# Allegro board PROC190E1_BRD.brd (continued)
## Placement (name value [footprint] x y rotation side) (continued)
R303  1.3K_1%  [RES0402_0-5]  21.9 58.09 180 top
R304  0E  [RES0603_0-75]  63.29 65.65 0 top
R305  0E  [RES0201_0-5]  29.77 57.67 0 top
R306  51K_1%  [RES0402_0-5]  25.61 73.76 0 top
R307  0E  [RES0201_0-5]  36.46 59.82 0 top
R308  1K_1%  [RES0402_0-5]  28.19 56.28 270 top
R310  0E  [RES0402_0-5]  50.51 57.91 180 top
R311  0E  [RES0402_0-5]  50.51 56.69 180 top
R313  30K_1%  [RES0402_0-5]  25.61 72.49 180 top
R314  0E  [RES0201_0-5]  30.37 73.38 270 bottom
R316  0.01E_1%  [RES_KRL3216T4_1206-4_0-7]  49.13 53.23 0 top
R317  0E  [RES0201_0-5]  42.36 52.69 180 top
R318  10K  [RES0402_0-5]  23.18 52 180 top
R319  0E  [RES0201_0-5]  64.31 58.72 0 bottom
R320  10K  [RES0201_0-5]  64.43 60.02 90 bottom
R321  10K  [RES0201_0-5]  51.6 27.95 180 top
R322  4.7K  [RES0201_0-5]  51.96 35.49 270 top
R323  2.2K  [RES0201_0-5]  52.16 28.96 180 top
R324  220E  [RES0402_0-5]  52.46 120.38 90 top
R326  4.7K  [RES0201_0-5]  52.8 35.49 270 top
R327  0.01E_1%  [RES_KRL3216T4_1206-4_0-7]  54.61 53.26 180 top
R328  10K  [RES0201_0-5]  53.18 28.24 90 top
R329  10K  [RES0201_0-5]  77.63 55.16 180 bottom
R330  220E  [RES0402_0-5]  54.23 30.72 90 top
R331  0E  [RES0402_0-5]  41.91 44.32 180 top
R333  10K  [RES0201_0-5]  54.65 27.94 270 top
R334  0.01E_1%  [RES_KRL3216T4_1206-4_0-7]  38.03 43.71 270 top
R335  0E  [RES0402_0-5]  41.91 43.05 180 top
R336  22E  [RES0201_0-5]  65.61 52.26 180 bottom
R337  0E  [RES0201_0-5]  65.33 51.98 90 bottom
R338  0E  [RES0402_0-5]  85.25 47.62 180 top
R340  0E  [RES0402_0-5]  86.7 49.16 270 top
R341  1K_1%  [RES0402_0-5]  122.28 46.89 0 top
R342  10K  [RES0201_0-5]  84.77 46.57 180 top
R343  1.5K  [RES0201_0-5]  86.32 46.57 180 top
R344  2.2K  [RES0201_0-5]  116 46.49 0 top
R345  0E  [RES0201_0-5]  119.68 46.49 0 top
R346  0E  [RES0201_0-5]  117.52 46.48 180 top
R347  100K  [RES0201_0-5]  128.93 46.48 270 bottom
R348  10K  [RES0201_0-5]  62.72 54.27 180 bottom
R349  22E  [RES0201_0-5]  66.03 56.78 0 bottom
R351  1.5K  [RES0201_0-5]  119.68 45.6 180 top
R352  0E  [RES0201_0-5]  118.51 45.29 270 top
R355  1K_1%  [RES0402_0-5]  89.46 44.56 270 top
R356  10K  [RES0201_0-5]  118.79 44.03 180 top
R357  10K  [RES0201_0-5]  62.44 22.85 90 top
R358  22E  [RES0201_0-5]  68.22 56.74 180 bottom
R359  22E  [RES0201_0-5]  71.7 53.62 0 bottom
R360  100K  [RES0201_0-5]  74.87 45.09 180 top
R361  4.7K  [RES0201_0-5]  70.03 28 270 top
R362  10K  [RES0201_0-5]  69.04 51.95 0 top
R363  10K  [RES0201_0-5]  70.79 51.95 180 top
R364  0E  [RES0201_0-5]  67.74 51.35 270 top
R366  0E  [RES0201_0-5]  71.35 50.97 180 top
R367  10K  [RES0201_0-5]  68.54 50.79 270 top
R371  10K  [RES0201_0-5]  52.19 39.6 90 top
R373  10K  [RES0201_0-5]  69.94 48.8 180 top
R374  10K  [RES0201_0-5]  43.91 28.51 270 top
R375  10K  [RES0201_0-5]  106.75 93.81 180 top
R377  0E  [RES0201_0-5]  80.74 135.3 270 top
R378  10K  [RES0201_0-5]  35.34 27.09 90 top
R381  10K  [RES0201_0-5]  34.33 33.48 270 top
R382  0E  [RES0402_0-5]  29.79 24.63 270 bottom
R385  0E  [RES0805_0-75]  72.92 2.55 180 top
R386  0E  [RES0201_0-5]  34.89 18.9 0 bottom
R390  0E  [RES0201_0-5]  34.88 19.81 0 bottom
R395  0E  [RES0603_0-75]  29.41 19.14 0 top
R398  16.5K_1%  [RES0402_0-5]  53.31 12.95 270 top
R399  0E  [RES0402_0-5]  48.97 12.17 270 top
R400  0E  [RES0402_0-5]  49.82 12.17 270 top
R401  3.48K_1%  [RES0201_0-5]  53.03 11.57 180 top
R402  470E  [RES0402_0-5]  45.06 10.86 90 top
R403  0E  [RES0603_0-75]  42.58 8.45 90 top
R404  0E  [RES0603_0-75]  27.81 8.39 90 top
R405  4.3K  [RES0402_0-5]  74.75 168.97 270 bottom
R406  4.3K  [RES0402_0-5]  73.48 168.97 270 bottom
R407  4.3K  [RES0402_0-5]  70.91 168.97 270 bottom
R408  4.3K  [RES0402_0-5]  69.64 168.97 270 bottom
R409  4.3K  [RES0402_0-5]  57.6 168.97 270 bottom
R410  4.3K  [RES0402_0-5]  56.33 168.97 270 bottom
R411  4.3K  [RES0402_0-5]  53.76 168.97 270 bottom
R412  4.3K  [RES0402_0-5]  52.49 168.97 270 bottom
R413  10K  [RES0402_0-5]  65.26 163.29 180 bottom
R414  0E  [RES0201_0-5]  67.13 162.02 180 bottom
R415  10K  [RES0402_0-5]  60.57 160.49 270 bottom
R416  10K  [RES0402_0-5]  61.94 160.49 90 bottom
R418  1K  [RES0402_0-5]  117.68 155.06 270 bottom
R419  1K  [RES0402_0-5]  116.34 155.06 90 bottom
R420  0E  [RES0201_0-5]  114.49 152.82 0 bottom
R421  0E  [RES0201_0-5]  96.93 152.82 0 bottom
R422  1K  [RES0402_0-5]  117.33 152.83 90 bottom
R423  1K  [RES0402_0-5]  116.02 152.83 270 bottom
R429  10K  [RES0201_0-5]  89.98 150.3 180 bottom
R430  10K  [RES0201_0-5]  108.45 150.13 180 bottom
R431  0E  [RES0402_0-5]  60.62 149.21 270 bottom
R432  0E  [RES0402_0-5]  58.46 149.01 270 bottom
R433  0E  [RES0402_0-5]  58.95 148.52 180 bottom
R435  0E  [RES0402_0-5]  58.46 148.03 90 bottom
R438  1K  [RES0201_0-5]  81.59 146.05 0 bottom
R439  10K  [RES0201_0-5]  81.59 143.51 180 bottom
R440  220E  [RES0402_0-5]  70.59 128.71 90 top
R441  0E  [RES0402_0-5]  69.73 133.99 270 top
R442  10K  [RES0201_0-5]  69.99 131.83 90 top
R443  10K  [RES0201_0-5]  69.23 111.33 90 bottom
R444  10K  [RES0201_0-5]  68.23 111.33 90 bottom
R445  10K  [RES0201_0-5]  67.23 111.33 90 bottom
R446  10K  [RES0201_0-5]  66.66 110.08 135 bottom
R447  10K  [RES0201_0-5]  70.06 106.06 180 bottom
R448  10K  [RES0201_0-5]  64.27 109.41 90 bottom
R449  10K  [RES0201_0-5]  65.5 109.06 180 bottom
R450  10K  [RES0201_0-5]  68.05 109.98 0 bottom
R451  10K  [RES0201_0-5]  67.13 106.27 180 bottom
R452  10K  [RES0201_0-5]  65.51 108.29 180 bottom
R453  22E  [RES0201_0-5]  67.99 107.44 0 bottom
R454  10K  [RES0201_0-5]  68.54 106.79 0 bottom
R456  10K  [RES0201_0-5]  88.43 126.94 180 bottom
R457  10K  [RES0201_0-5]  93.54 126.78 0 bottom
R461  10K  [RES0201_0-5]  85.62 125.47 0 bottom
R464  4.7K  [RES0201_0-5]  132.17 141.15 90 top
R465  4.7K  [RES0201_0-5]  132.94 141.15 90 top
R476  33E  [RES0201_0-5]  43.65 114.18 90 bottom
R480  10K  [RES0201_0-5]  22.51 65.62 270 bottom
R482  4.7K  [RES0201_0-5]  38.18 113.97 270 top
R483  33E  [RES0201_0-5]  48.64 113.29 270 bottom
R485  10K  [RES0201_0-5]  45.54 112.81 90 bottom
R487  100E_1%  [RES0402_0-5]  44.04 112.31 180 bottom
R489  10K  [RES0201_0-5]  47.26 108.84 270 bottom
R490  0E  [RES0201_0-5]  46.07 108.84 270 bottom
R491  0E  [RES0402_0-5]  84.97 100.29 90 bottom
R492  0E  [RES0402_0-5]  83.73 100.29 90 bottom
R493  0E  [RES0402_0-5]  81.18 100.29 90 bottom
R494  0E  [RES0402_0-5]  79.34 98.28 90 bottom
R495  0E  [RES0402_0-5]  86.81 98.28 90 bottom
R498  0E  [RES0402_0-5]  86.22 100.29 90 bottom
R499  0E  [RES0402_0-5]  80.59 98.28 90 bottom
R500  0E  [RES0402_0-5]  73 99.15 90 bottom
R504  1K  [RES0402_0-5]  67.26 93.34 90 bottom
R505  0E  [RES0201_0-5]  55.28 61.56 180 bottom
R506  0E  [RES0402_0-5]  86.49 73.38 0 bottom
R507  10K  [RES0201_0-5]  13.05 83.08 270 bottom
R509  0E  [RES0201_0-5]  83.93 89.3 0 bottom
R510  10K  [RES0201_0-5]  13.16 90.37 270 bottom
R511  10K  [RES0201_0-5]  13.45 92.58 90 bottom
R512  10K  [RES0201_0-5]  13.54 85.27 90 bottom
R513  10K  [RES0201_0-5]  13.94 83.08 270 bottom
R515  10K  [RES0201_0-5]  13.96 90.37 270 bottom
R516  10K  [RES0201_0-5]  14.34 92.58 90 bottom
R517  10K  [RES0201_0-5]  14.34 85.27 90 bottom
R518  0E  [RES0201_0-5]  85.59 88.32 0 top
R519  10K  [RES0201_0-5]  14.76 90.37 270 bottom
R520  1K_1%  [RES0402_0-5]  33.73 98.17 90 bottom
R521  1K_1%  [RES0402_0-5]  32.46 98.17 90 bottom
R522  1K_1%  [RES0402_0-5]  31.19 98.17 90 bottom
R523  1K_1%  [RES0402_0-5]  29.92 98.17 90 bottom
R524  10K  [RES0201_0-5]  14.83 83.08 270 bottom
R525  10K  [RES0201_0-5]  15.14 85.27 90 bottom
R526  10K  [RES0201_0-5]  15.23 92.58 90 bottom
R527  0E  [RES0201_0-5]  82.48 89.65 0 bottom
R528  0E  [RES0201_0-5]  83.27 90.46 0 bottom
R529  0E  [RES0201_0-5]  82.56 88 0 bottom
R530  0E  [RES0201_0-5]  83.9 87.44 0 bottom
R531  10K  [RES0201_0-5]  28.66 95.45 270 bottom
R533  10K  [RES0201_0-5]  31.27 94.59 180 bottom
R534  10K  [RES0201_0-5]  30.13 94.58 90 bottom
R535  0E  [RES0201_0-5]  85.92 86.44 270 top
R536  10K  [RES0201_0-5]  28.94 94.4 0 bottom
R537  0E  [RES0201_0-5]  81.8 86.65 0 bottom
R538  0E  [RES0201_0-5]  86.56 75.37 0 bottom
R539  0E  [RES0402_0-5]  55.68 51.42 270 bottom
R540  0E  [RES0402_0-5]  54.54 51.42 270 bottom
R541  0E  [RES0402_0-5]  88.36 84.67 90 top
R542  22E  [RES0201_0-5]  63.37 87.39 270 top
R543  10K_1%  [RES0603_0-75]  60.59 85.55 0 bottom
R544  22E  [RES0201_0-5]  30.31 93.15 270 bottom
R545  1.1K_1%  [RES0603_0-5]  60.59 83.98 180 bottom
R546  4.7K  [RES0201_0-5]  46.14 72.88 270 bottom
R547  4.7K  [RES0201_0-5]  47.08 72.88 270 bottom
R548  0E  [RES0402_0-5]  85.82 83.94 0 top
R549  10K  [RES0201_0-5]  29.48 91.44 180 bottom
R550  10K  [RES0201_0-5]  46.64 74.27 0 bottom
R551  4.7K  [RES0201_0-5]  18.15 68.83 90 bottom
R552  4.7K  [RES0201_0-5]  16.88 68.83 90 bottom
R553  499E_1%  [RES0402_0-5]  85.82 82.87 0 top
R554  10K  [RES0201_0-5]  30.15 90.34 270 bottom
R555  10K  [RES0201_0-5]  31.02 90.46 90 bottom
R556  10K  [RES0201_0-5]  28.8 90.68 180 bottom
R558  0E  [RES0402_0-5]  84.96 79.2 180 bottom
R559  10K  [RES0201_0-5]  31.49 107.68 180 top
R560  10K_1%  [RES0201_0-5]  81.02 70.26 270 top
R561  10K  [RES0201_0-5]  107.57 70.81 180 bottom
R562  10K  [RES0201_0-5]  107.21 74.41 90 bottom
R564  4.7K  [RES0201_0-5]  61.05 87.91 90 bottom
R565  10K  [RES0201_0-5]  107.57 70.17 0 bottom
R566  22E  [RES0201_0-5]  37 86.07 270 bottom
R568  1M  [RES0402_0-5]  56.34 74.75 90 bottom
R569  10K  [RES0201_0-5]  34.89 85.74 0 bottom
R571  0E  [RES0402_0-5]  32.97 67.3 0 bottom
R572  0E  [RES0402_0-5]  32.94 68.55 0 bottom
R575  10K  [RES0201_0-5]  109.33 71.98 90 bottom
R576  100E_1%  [RES0402_0-5]  28.11 82.23 0 bottom
R578  1K  [RES0402_0-5]  19.91 69.03 180 bottom
R579  0E  [RES0201_0-5]  16.97 78.52 270 bottom
R580  0E  [RES0201_0-5]  17.86 78.52 270 bottom
R581  0.01E_1%  [RES_KRL3216T4_1206-4_0-7]  50.14 64.65 90 bottom
R582  4.7K  [RES0201_0-5]  15.89 79.33 90 bottom
R583  4.7K  [RES0201_0-5]  16.57 67.53 0 bottom
R584  0E  [RES0402_0-5]  50.33 58.22 90 bottom
R585  0E  [RES0402_0-5]  49.19 58.22 90 bottom
R586  0E  [RES0201_0-5]  30.08 58.14 270 bottom
R590  10K  [RES0201_0-5]  46.32 35.26 90 bottom
R591  10K  [RES0201_0-5]  47.21 35.26 270 bottom
R592  4.7K  [RES0201_0-5]  47.97 36.44 180 bottom
R593  4.7K  [RES0201_0-5]  48.96 36.28 270 bottom
R596  0E  [RES0201_0-5]  49.01 47.76 270 bottom
R597  10K  [RES0201_0-5]  49.01 46.14 270 bottom
R598  4.7K  [RES0201_0-5]  87.7 77.14 180 bottom
R601  10K  [RES0201_0-5]  114.04 49.13 180 bottom
R602  10K  [RES0201_0-5]  112.29 49.13 0 bottom
R603  4.7K  [RES0201_0-5]  78.71 64.01 180 bottom
R604  0E  [RES0201_0-5]  115.65 48.25 180 bottom
R605  0E  [RES0201_0-5]  111.73 48.15 0 bottom
R606  10K  [RES0201_0-5]  114.55 47.97 270 bottom
R607  10K  [RES0201_0-5]  113.15 45.84 0 bottom
R608  0E  [RES0201_0-5]  51.64 39.15 270 bottom
R609  12K_1%  [RES0402_0-5]  60.24 26.39 90 bottom
R610  0E  [RES0805_0-75]  15.06 57.98 180 bottom
R611  4.7K  [RES0201_0-5]  60.72 30.19 270 bottom
R612  4.7K  [RES0201_0-5]  60.82 31.62 0 bottom
R613  10K  [RES0201_0-5]  61.03 29 0 bottom
R614  10K  [RES0201_0-5]  61.03 28.12 180 bottom
R615  10K  [RES0201_0-5]  57.6 113.69 0 top
R616  10K  [RES0402_0-5]  127.05 41.7 0 bottom
R618  1K  [RES0402_0-5]  127.05 40.43 180 bottom
R620  2.2K  [RES0201_0-5]  82.72 39.8 270 bottom
R621  0E  [RES0201_0-5]  83.53 39.79 90 bottom
R622  10K  [RES0402_0-5]  123.38 39.53 0 bottom
R623  0E  [RES0201_0-5]  96.15 39.1 180 bottom
R624  0E  [RES0201_0-5]  112.71 38.99 0 bottom
R625  1K  [RES0402_0-5]  123.38 38.26 180 bottom
R626  10K  [RES0402_0-5]  119.08 35.33 90 bottom
R627  0E  [RES0201_0-5]  33.11 32.66 90 bottom
R628  1K  [RES0402_0-5]  126.17 36.82 90 bottom
R629  1K  [RES0402_0-5]  120.28 35.33 270 bottom
R630  10K  [RES0402_0-5]  125.05 36.82 270 bottom
R631  4.7K  [RES0201_0-5]  70.32 25.38 0 bottom
R632  100K_1%  [RES0402_0-5]  90.51 34.14 90 bottom
R633  0E  [RES0201_0-5]  33.39 30.12 90 bottom
R634  316K_1%  [RES0402_0-5]  89.24 33.16 90 bottom
R635  10K  [RES0201_0-5]  71.92 25.15 180 bottom
R636  10K  [RES0201_0-5]  72.77 26.05 0 bottom
R637  10K  [RES0201_0-5]  89.21 31.55 180 bottom
R638  10K  [RES0402_0-5]  85.89 34.27 270 bottom
R639  1K  [RES0402_0-5]  87.13 34.27 90 bottom
R641  10K  [RES0402_0-5]  99 33.43 270 bottom
R642  1K  [RES0402_0-5]  97.86 33.43 90 bottom
R643  0E  [RES0805_0-75]  18.11 63.47 90 bottom
R644  10K  [RES0201_0-5]  39.92 26.88 270 bottom
R645  10K  [RES0201_0-5]  39.16 26.88 270 bottom
R646  10K  [RES0201_0-5]  42.61 26.67 180 bottom
R651  0E  [RES0201_0-5]  42.33 25.5 90 bottom
R652  0E  [RES0201_0-5]  41.57 25.5 90 bottom
R653  0E  [RES0201_0-5]  40.81 25.5 90 bottom
R654  0E  [RES0201_0-5]  40.05 25.5 90 bottom
R655  0E  [RES0201_0-5]  39.29 25.5 270 bottom
R656  0E  [RES0201_0-5]  38.52 25.5 270 bottom
R657  0E  [RES0201_0-5]  37.76 25.5 270 bottom
R658  10K  [RES0201_0-5]  35.26 25.08 270 bottom
R660  10K  [RES0201_0-5]  36.59 24.77 0 bottom
R662  100K  [RES0201_0-5]  44.5 23.88 90 bottom
R664  10K  [RES0201_0-5]  34.91 23.66 270 bottom
R665  0E  [RES0402_0-5]  45.68 22.51 180 bottom
R669  1K  [RES0402_0-5]  46.16 19.69 0 bottom
R672  100K  [RES0402_0-5]  47.14 18.29 0 bottom
R673  0E  [RES0201_0-5]  45.49 18.29 0 bottom
R674  0E  [RES0201_0-5]  34.88 17.98 0 bottom
R675  10K_1%  [RES0201_0-5]  57.92 17.65 90 bottom
R676  10K_1%  [RES0201_0-5]  50.12 16.56 270 bottom
R677  10K  [RES0201_0-5]  49.7 15.62 180 bottom
R678  0E  [RES0201_0-5]  39.49 15.61 180 bottom
R679  10K_1%  [RES0201_0-5]  40.55 15.24 90 bottom
R680  10K  [RES0201_0-5]  52.39 14.46 180 bottom
R681  100K_1%  [RES0402_0-5]  40.68 13.56 270 bottom
R682  100K_1%  [RES0402_0-5]  39.41 13.56 270 bottom
R684  4.7K  [RES0201_0-5]  14.93 124.44 0 top
R685  4.7K  [RES0201_0-5]  14.93 123.64 0 top
R3028  10K  [RES0402_0-5]  25.6 14.8 90 top
R3651  24.9K_1%  [RES0402_0-5]  18.2 10.21 270 top
R3652  33K_1%  [RES0603_0-75]  23.11 12.01 0 top
R3653  10K  [RES0402_0-5]  20.72 12.04 270 top
R3661  1K  [RES0201_0-5]  19.8 8.7 0 top
R3720  100K  [RES0402_0-5]  19.47 10.21 90 top
R3723  47.5K_1%  [RES0402_0-5]  55.05 80.56 270 bottom
R3724  21K_1%  [RES0402_0-5]  53.13 78.24 180 bottom
R3725  10K  [RES0201_0-5]  51.01 78 90 bottom
R3726  10K  [RES0201_0-5]  49.95 78.65 270 bottom
R3727  100K  [RES0402_0-5]  22.8 13.82 90 top
R3731  0E  [RES0402_0-5]  66.52 81.51 0 bottom
R3732  0E  [RES0201_0-5]  66.26 73.66 180 top
R3733  0E  [RES0201_0-5]  68.8 73.66 0 top
R3736  1K  [RES0201_0-5]  113.54 86.36 0 top
R3933  470E  [RES0402_0-5]  31.77 13.11 180 top
R5213  10K  [RES0201_0-5]  130.03 67.15 0 top
R5215  10K  [RES0201_0-5]  93.24 82.52 0 bottom
R5216  1K  [RES0201_0-5]  93.24 82.52 0 top
R5635  33.2K_1%  [RES0402_0-5]  35.87 162.32 90 top
R5636  3.32K_1%  [RES0402_0-5]  34.1 165.04 180 top
R5637  0E  [RES0402_0-5]  37.39 162.57 90 top
R5638  10K  [RES0402_0-5]  42.51 160.74 270 top
R5639  0E  [RES0402_0-5]  39.88 162.66 90 top
R5640  0E  [RES0402_0-5]  78.48 99.55 90 top
R5641  0E  [RES0402_0-5]  78.38 151.57 90 top
R5642  0E  [RES0402_0-5]  93.69 150.72 90 top
R5643  0E  [RES0402_0-5]  98.42 150.73 90 bottom
R5644  0E  [RES0402_0-5]  113.48 150.72 90 top
R5645  0E  [RES0402_0-5]  75.93 99.5 90 top
R5646  22E  [RES0402_0-5]  75.34 97.45 270 top
R5647  0E  [RES0402_0-5]  72.41 97.19 90 bottom
R5648  22E  [RES0402_0-5]  85.56 98.28 270 bottom
R5649  0E  [RES0402_0-5]  82.2 79.39 180 bottom
R5650  33E  [RES0402_0-5]  61.9 82.06 180 top
R5651  22E  [RES0402_0-5]  77.83 97.45 270 top
R5652  0E  [RES0402_0-5]  77.23 99.55 90 top
R5653  22E  [RES0402_0-5]  70.68 95.49 180 top
R5654  0E  [RES0402_0-5]  72.85 97.45 90 top
R5655  0E  [RES0402_0-5]  68.13 95.52 0 top
R5656  0E  [RES0402_0-5]  79.72 99.55 90 top
R5657  0E  [RES0402_0-5]  80.97 99.55 90 top
R5658  0E  [RES0402_0-5]  80.33 97.45 90 top
R5659  22E  [RES0201_0-5]  84.27 74.13 180 top
R5660  0E  [RES0402_0-5]  76.14 97.19 90 bottom
R5661  0E  [RES0402_0-5]  73.65 97.19 90 bottom
R5662  0E  [RES0402_0-5]  77.39 97.19 90 bottom
R5663  0E  [RES0402_0-5]  74.25 99.15 90 bottom
R5664  0E  [RES0402_0-5]  74.9 97.19 90 bottom
R5665  0E  [RES0402_0-5]  76.74 99.15 90 bottom
R5666  0E  [RES0402_0-5]  75.53 99.15 90 bottom
R5667  0E  [RES0402_0-5]  69.92 97.19 90 bottom
R5668  22E  [RES0402_0-5]  78.02 99.14 270 bottom
R5669  22E  [RES0402_0-5]  70.53 99.15 270 bottom
R5670  33E  [RES0402_0-5]  66.74 79.19 270 bottom
R5671  0E  [RES0402_0-5]  58.9 81.29 0 top
R5672  0E  [RES0402_0-5]  73.44 99.5 90 top
R5673  0E  [RES0402_0-5]  69.32 99.15 90 bottom
R5674  0E  [RES0402_0-5]  74.74 99.5 90 top
R5675  0E  [RES0402_0-5]  71.77 99.15 90 bottom
R5676  0E  [RES0402_0-5]  74.09 97.45 90 top
R5677  22E  [RES0402_0-5]  67.73 99.14 270 bottom
R5681  10K  [RES0201_0-5]  113.75 101.51 270 bottom
R5682  0E  [RES0402_0-5]  67.64 96.01 90 top
R5683  22E  [RES0402_0-5]  70.19 95.98 270 top
R5684  10K_1%  [RES0402_0-5]  104.03 114.7 270 bottom
R5685  0E  [RES0603_0-75]  80.82 73.43 180 top
R5686  22E  [RES0201_0-5]  97.93 55.18 0 top
R5687  10K  [RES0201_0-5]  112.5 47.07 180 top
R5688  10K  [RES0201_0-5]  68.44 49.39 270 top
R5689  0E  [RES0402_0-5]  88.64 76.7 90 top
R5692  10K  [RES0402_0-5]  38.52 154.19 0 top
R5693  10K  [RES0201_0-5]  52.72 97.69 90 bottom
R5694  0E  [RES0201_0-5]  60.42 91.15 0 bottom
R5695  0E  [RES0201_0-5]  60.42 92.13 0 bottom
R5696  0E  [RES0201_0-5]  53.92 96.75 270 bottom
R5697  0E  [RES0201_0-5]  57.64 111.38 270 top
R5698  10K  [RES0201_0-5]  56.07 105.79 0 top
R5699  10K  [RES0201_0-5]  59.1 109.3 270 top
R5709  1K  [RES0402_0-5]  66.13 96.09 0 bottom
R5710  10K  [RES0201_0-5]  55.97 100.23 180 bottom
R5711  10K  [RES0201_0-5]  60.8 96.82 0 bottom
R5712  10K  [RES0201_0-5]  57.96 99.97 90 bottom
R5713  10K  [RES0201_0-5]  60.8 95.68 0 bottom
R5714  10K  [RES0201_0-5]  60.44 98.55 0 bottom
R5715  10K  [RES0201_0-5]  57.02 98.02 90 bottom
R5716  10K  [RES0201_0-5]  57.7 94.54 180 bottom
R5717  10K  [RES0201_0-5]  57.45 101.47 180 bottom
R5718  0E  [RES0402_0-5]  83.08 98.28 90 bottom
R5719  0E  [RES0402_0-5]  84.32 98.28 90 bottom
R5720  0E  [RES0402_0-5]  67.93 62.17 270 top
R5721  0E  [RES0402_0-5]  70.63 63.09 270 top
R5722  0E  [RES0402_0-5]  74.36 61.31 270 top
R5723  0E  [RES0402_0-5]  75.61 63.09 270 top
R5724  0E  [RES0402_0-5]  66.77 60.88 270 top
R5725  0E  [RES0402_0-5]  69.08 60.95 270 top
R5726  0E  [RES0402_0-5]  73.12 63.09 270 top
R5727  0E  [RES0402_0-5]  71.87 61.31 270 top
R5728  0E  [RES0402_0-5]  74 72.72 270 bottom
R5730  0E  [RES0201_0-5]  41.03 97.54 270 bottom
R5731  0E  [RES0201_0-5]  39.91 97.52 270 bottom
R5732  0E  [RES0201_0-5]  76.46 61.62 270 top
R5733  10K  [RES0201_0-5]  79.88 48.77 0 top
R5734  33.2E_1%  [RES0201_0-5]  77.56 49.73 90 top
R5735  10K  [RES0201_0-5]  46.25 121.76 90 top
R5736  10K  [RES0402_0-5]  25.11 47.3 270 top
R5737  100K  [RES0402_0-5]  28.21 49.83 0 top
R5738  0E  [RES0402_0-5]  72.56 76.83 270 bottom
R5740  10K  [RES0402_0-5]  24.07 14.8 270 top
R5741  10K  [RES0402_0-5]  91.58 107.46 270 top
R5742  10K  [RES0402_0-5]  92.85 97.14 90 top
R5743  0E  [RES0402_0-5]  90.96 97.17 0 top
R5744  10K  [RES0402_0-5]  51.27 138.17 90 top
R5745  10K  [RES0402_0-5]  52.54 138.17 270 top
R5746  1K  [RES0402_0-5]  53.03 126.86 0 top
R5747  0E  [RES0603_0-75]  47.54 64.72 90 bottom
R5748  0E  [RES0603_0-75]  46.8 65.46 0 bottom
R5750  0E  [RES0402_0-5]  60.35 83.53 180 top
R5751  0E  [RES0402_0-5]  60.34 84.8 180 top
R5752  22E  [RES0402_0-5]  64.49 98.04 180 bottom
R5753  10K  [RES0201_0-5]  55.49 94.76 0 bottom
R5754  10K  [RES0201_0-5]  55.16 97.05 270 bottom
R5756  10K  [RES0201_0-5]  61.52 122.55 90 top
R5757  0E  [RES0402_0-5]  67.6 95.62 90 bottom
R5758  0E  [RES0201_0-5]  95.83 82.3 270 top
R5759  100K  [RES0402_0-5]  105.61 83.61 270 top
R5760  100K  [RES0402_0-5]  56.2 111.18 0 top
R5761  47K_1%  [RES0402_0-5]  104.57 135.43 90 top
R5764  100K  [RES0402_0-5]  28.37 118.64 0 top
R5766  4.7K  [RES0201_0-5]  21.15 63.45 270 top
R5767  10K  [RES0201_0-5]  35.3 33.47 270 top
R5773  1.1K_1%  [RES0603_0-5]  33.6 53.32 270 top
R5774  10K_1%  [RES0603_0-75]  30.62 54.45 270 top
R5775  0E  [RES0201_0-5]  121.62 149.18 0 top
R5776  0E  [RES0201_0-5]  24.96 115.52 90 top
R5777  10K  [RES0201_0-5]  89.15 30.61 0 bottom
R5778  0E  [RES0201_0-5]  58.89 61.25 0 bottom
R5780  0E  [RES0402_0-5]  56.98 70.31 180 bottom
R5781  0E  [RES0402_0-5]  56.98 71.37 180 bottom
R5782  0E  [RES0201_0-5]  44.02 69.17 270 bottom
R5784  0E  [RES0402_0-5]  44.15 78.71 90 bottom
R5785  0E  [RES0402_0-5]  45.38 78.74 90 bottom
R5786  0.01E_1%  [RES_KRL3216T4_1206-4_0-7]  54.55 77.75 180 top
R5787  0.01E_1%  [RES_KRL3216T4_1206-4_0-7]  44.75 82.07 0 bottom
R5788  0E  [RES0603_0-75]  79.34 73.43 0 top
R5789  10K  [RES0201_0-5]  107.66 55.63 270 top
R5790  10K  [RES0201_0-5]  110.38 54.79 0 top
R5791  0E  [RES0201_0-5]  115.66 54.69 0 top
R5792  0E  [RES0201_0-5]  110.84 56.72 270 top
R5793  0E  [RES0201_0-5]  107.82 60.22 180 top
R5795  10K  [RES0201_0-5]  99.71 57.38 270 top
R5796  10K  [RES0201_0-5]  98.87 58.34 180 top
R5797  10K  [RES0201_0-5]  85.62 134.85 90 top
R5798  10K  [RES0201_0-5]  89.43 135.48 180 top
R5799  10K  [RES0201_0-5]  60.39 41.91 180 top
R5800  10K  [RES0201_0-5]  69.18 44.17 180 top
R5805  0E  [RES0201_0-5]  15.56 14.78 270 top
R5806  10K  [RES0201_0-5]  64.46 53.7 0 top
R5808  10K  [RES0201_0-5]  79.85 49.53 0 top
R5810  10K  [RES0201_0-5]  64.65 97.1 180 bottom
R5811  0E  [RES0402_0-5]  86.11 77.93 180 top
R5812  0E  [RES0402_0-5]  86.11 79.04 180 top
R5813  0E  [RES0402_0-5]  86.11 80.16 180 top
R5814  0E  [RES0402_0-5]  84.91 80.26 180 bottom
R5815  0E  [RES0402_0-5]  82.4 82.04 180 bottom
R5816  0E  [RES0402_0-5]  82.32 80.39 180 bottom
R5817  0E  [RES0402_0-5]  86.11 81.28 180 top
R5818  0E  [RES0402_0-5]  85.4 81.56 180 bottom
R5819  0E  [RES0402_0-5]  85.5 84.45 180 bottom
R5820  10K  [RES0201_0-5]  56.07 104.72 180 top
R5821  10K  [RES0201_0-5]  67.61 129.36 180 top
R5822  10K  [RES0201_0-5]  112.78 92.53 180 top
R5823  10K  [RES0201_0-5]  125.76 66.75 90 top
R5824  10K  [RES0201_0-5]  71.26 48.23 90 top
R5825  10K  [RES0201_0-5]  115.59 45.9 180 bottom
R5826  0E  [RES0402_0-5]  71.22 105.21 180 bottom
R5827  0E  [RES0402_0-5]  70.73 104.72 90 bottom
R5828  0E  [RES0402_0-5]  34.11 55.88 0 bottom
R5829  0E  [RES0402_0-5]  34.27 54.79 0 bottom
RA2  1K  [RESA_EXB_0201-4_0-5]  81.32 106.71 0 bottom
RA3  0E  [RESA_EXB_0201-4_0-5]  65.42 102.76 180 top
RA4  0E  [RESA_EXB_0201-4_0-5]  67.84 102.76 180 top
RA5  1K  [RESA_EXB_0201-4_0-5]  84.34 106.71 0 bottom
RA6  1K  [RESA_EXB_0201-4_0-5]  78.02 108.13 0 bottom
RA7  1K  [RESA_EXB_0201-4_0-5]  87.36 106.71 0 bottom
RA8  0E  [RESA_EXB_0201-4_0-5]  63.06 92.66 0 bottom
RA9  0E  [RESA_EXB_0201-4_0-5]  65.19 92.66 0 bottom
SW1  416131160808  [SW16_416131160808_460X230_SMD_2-7]  91.49 122.66 0 top
SW2  416131160808  [SW16_416131160808_460X230_SMD_2-7]  78.99 122.66 0 top
SW3  218-2LPST  [SW4_49-99_150X230_SMD_2-7]  41.2 101.1 270 top
SW5  7914G-1-000E  [SW4_100X216_200X200_SMD_4-2]  31.88 113.5 0 top
SW6  7914G-1-000E  [SW4_100X216_200X200_SMD_4-2]  60.63 118.28 270 top
SW7  7914G-1-000E  [SW4_100X216_200X200_SMD_4-2]  47.79 40.94 270 top
SW8  7914G-1-000E  [SW4_100X216_200X200_SMD_4-2]  103.72 97.15 270 top
SW9  TDA01H0SB1R  [SW_TDA01H0S_240X90_SMD_2-3]  108.13 86.36 180 top
SW10  7914G-1-000E  [SW4_100X216_200X200_SMD_4-2#2]  60.25 127.16 0 top
SW11  CAS-120TA  [SW3_CAS-120TA_215X100_SMD]  123.13 57.13 0 top
TP1  THRU HOLE  [TP_40X65]  33.06 152.97 0 top
TP2  THRU HOLE  [TP_40X65]  132.63 44.53 0 top
TP5  -  [TP30_SMD]  66.86 156.1 90 top
TP6  -  [TP30_SMD]  69.22 155.05 90 top
TP8  -  [TP30_SMD]  67.75 153.6 270 top
TP9  -  [TP30_SMD]  69.22 153.6 270 top
TP11  -  [TP30_SMD]  97.53 152.82 180 top
TP12  -  [TP30_SMD]  79.93 152.82 180 top
TP14  -  [TP30_SMD]  114.65 152.63 180 top
TP17  -  [TP30_SMD]  84.76 149.48 180 top
TP18  -  [TP30_SMD]  86.1 149.48 180 top
TP19  -  [TP30_SMD]  102.16 149.48 180 top
TP20  -  [TP30_SMD]  103.5 149.48 180 top
TP21  -  [TP20_SMD]  132.71 77.41 90 top
TP22  -  [TP30_SMD]  85.42 148.26 180 top
TP23  -  [TP30_SMD]  102.82 148.26 180 top
TP25  -  [TP30_SMD]  49.86 145.55 90 top
TP26  -  [TP30_SMD]  46.52 145.18 90 top
TP27  -  [TP30_SMD]  48.19 145.15 270 top
TP31  -  [TP30_SMD]  50.24 143.25 270 top
TP32  -  [TP30_SMD]  85.13 55.71 0 top
TP33  -  [TP30_SMD]  85.14 54.23 0 top
TP36  -  [TP30_SMD]  87.26 54.71 180 top
TP37  -  [TP30_SMD]  89.63 54.82 0 top
TP38  -  [TP30_SMD]  90.77 61.73 0 top
TP39  -  [TP30_SMD]  91.84 62.33 0 top
TP40  THRU HOLE  [TP_40X65]  131.04 154.95 0 top
TP41  -  [TP40_SMD]  66.85 130.99 0 top
TP42  -  [TP40_SMD]  43.4 123.62 0 top
TP44  -  [TP40_SMD]  69.97 139.35 0 top
TP45  -  [TP20_SMD]  91.71 129.93 180 top
TP46  -  [TP20_SMD]  43.82 68.74 0 top
TP49  -  [TP20_SMD]  96.22 92.8 180 top
TP50  -  [TP20_SMD]  45.53 73.77 0 top
TP51  -  [TP20_SMD]  27.62 92.05 90 top
TP52  -  [TP20_SMD]  56.52 78.77 0 top
TP53  -  [TP20_SMD]  37.19 71.06 0 top
TP54  -  [TP20_SMD]  47.89 64.37 180 top
TP55  -  [TP20_SMD]  52.39 76.49 180 top
TP56  -  [TP20_SMD]  49.64 64.46 0 top
TP58  -  [TP20_SMD]  20.83 79.96 180 top
TP59  -  [TP30_SMD]  120.21 48.15 0 top
TP60  -  [TP20_SMD]  51.42 63.72 90 top
TP61  -  [TP20_SMD]  24.29 80.27 180 top
TP62  -  [TP20_SMD]  27.92 79.82 180 top
TP63  -  [TP20_SMD]  29.34 77.76 180 top
TP64  -  [TP20_SMD]  27.82 78.5 180 top
TP65  -  [TP30_SMD]  87.32 45.3 0 top
TP66  -  [TP20_SMD]  31.83 77.54 180 top
TP67  -  [TP20_SMD]  49.65 60.38 0 top
TP68  -  [TP20_SMD]  24.93 76.5 270 top
TP69  -  [TP20_SMD]  65.04 65.65 0 top
TP70  -  [TP20_SMD]  51.24 60.7 0 top
TP71  -  [TP20_SMD]  16.93 78.65 0 top
TP72  -  [TP30_SMD]  28.27 64.29 90 top
TP73  -  [TP30_SMD]  27.05 62.83 90 top
TP74  -  [TP20_SMD]  35.27 55.57 0 top
TP75  -  [TP20_SMD]  57.84 84.48 0 top
TP76  -  [TP20_SMD]  52.19 40.89 180 top
TP77  THRU HOLE  [TP_40X65]  95.55 144.5 0 top
TP78  -  [TP20_SMD]  31.43 73.56 270 top
TP79  -  [TP20_SMD]  51.09 51.82 0 top
TP80  -  [TP40_SMD]  22.22 61.75 0 top
TP81  -  [TP40_SMD]  25.43 61.95 0 top
TP83  -  [TP20_SMD]  53.08 56.93 0 top
TP85  THRU HOLE  [TP_40X65]  121.34 103.28 0 top
TP86  -  [TP20_SMD]  35.73 42.8 90 top
TP87  -  [TP30_SMD]  123.47 47.79 0 top
TP89  -  [TP30_SMD]  127.43 47.07 0 top
TP91  -  [TP30_SMD]  126.03 46.64 0 top
TP92  -  [TP20_SMD]  114.86 45.85 270 top
TP93  -  [TP30_SMD]  90.73 46.31 90 top
TP94  -  [TP30_SMD]  111.05 46.03 0 top
TP95  -  [TP30_SMD]  81.89 45.54 90 top
TP96  -  [TP20_SMD]  60.09 7.73 90 top
TP97  -  [TP20_SMD]  68.78 27.51 180 top
TP98  -  [TP30_SMD]  74.21 44.04 90 top
TP99  -  [TP30_SMD]  89.6 48.57 90 top
TP100  -  [TP20_SMD]  88.55 54.59 0 top
TP103  -  [TP20_SMD]  66.41 45.97 270 top
TP104  -  [TP20_SMD]  26.1 16.69 180 top
TP106  -  [TP40_SMD]  27.81 61.36 0 top
TP107  -  [TP20_SMD]  36.05 11.14 90 top
TP108  -  [TP20_SMD]  50.89 9.72 90 top
TP109  -  [TP30_SMD]  98.41 152.55 0 bottom
TP110  -  [TP30_SMD]  111 149.48 0 bottom
TP111  -  [TP30_SMD]  109.65 149.48 0 bottom
TP112  -  [TP30_SMD]  93.6 149.48 0 bottom
TP113  -  [TP30_SMD]  92.25 149.48 0 bottom
TP114  -  [TP30_SMD]  110.34 148.51 0 bottom
TP115  -  [TP30_SMD]  93.19 148.26 0 bottom
TP116  -  [TP20_SMD]  106.71 72.93 270 bottom
TP117  -  [TP20_SMD]  71.76 23.85 90 bottom
TP585  -  [TP30_SMD]  41.22 162.4 0 top
TP586  -  [TP20_SMD]  62.54 92.15 0 top
TP587  -  [TP20_SMD]  84.96 106.97 0 top
TP588  -  [TP30_SMD]  117.12 48.39 0 top
TP589  -  [TP30_SMD]  121.5 43.92 0 top
TP590  -  [TP30_SMD]  82.95 46.35 0 top
TP591  -  [TP30_SMD]  89.04 47.15 0 top
TP592  -  [TP20_SMD]  62.44 72.82 0 top
TP593  -  [TP20_SMD]  36.43 164.13 180 top
TP594  -  [TP20_SMD]  63.49 93.27 270 top
TP597  -  [TP20_SMD]  56.23 85.7 90 top
U2  SN74LVC1G11DRYR  [SON6_SN74LVC2G17_40X60_0-6]  127.38 68.35 270 top
U4  TPS22918DBVR  [SOT23-6]  123.22 69.13 90 top
U5  TAD5212IRGER  [QFN24_TAD5212IRGER_160X160_1]  85.17 153.07 0 top
U6  TAD5212IRGER  [QFN24_TAD5212IRGER_160X160_1]  102.57 153.07 0 top
U7  PCM6240QRTVRQ1  [QFN32_19-68_200X200_0-8_EP3-6]  65.96 149.55 90 top
U8  PCM6240QRTVRQ1  [QFN32_19-68_200X200_0-8_EP3-6]  53.79 148.27 270 top
U10  TPD6E001RSER  [UQFN10_19-68_80X60_0-6]  127.6 76.15 0 top
U11  TCA9406DCUR  [VSSOP8_19-68_85X95]  111.47 145.86 0 top
U12  TPD2E001DRLR  [SOT553-5_0-6]  119.38 77.63 0 top
U14  SN74LVC1G08DBVRE4  [SOT23-5]  76.43 138.86 180 top
U15  CDCE6214RGET  [WFQFN24_CDCE6214-Q1_160X160_0-9]  89.45 57.89 0 top
U18  TCA6416ARTWR  [WQFN24_19-68_160X160]  65.3 135.11 0 top
U21  TCA6424ARGJR  [QFN32_19-68_200X200]  101.43 139.6 180 top
U23  SN74LVC1G08DBVRE4  [SOT23-5]  81.69 138.05 90 top
U25  TCA9517DR  [SOIC8_1-8]  51.57 107.95 270 top
U26  SN74LVC1G08DBVRE4  [SOT23-5]  112.69 94.94 0 top
U27  SN74LVC1G08DBVRE4  [SOT23-5]  67.7 126.88 180 top
U28  S28HS512TGABHM010  [BGA24_39-37_240X310_1]  66.73 107.99 180 top
U29  SN74AVC2T244DQMR  [X2SON8_15-74_70X50]  101.96 58.98 270 top
U39  TXS0102DQER  [X2SON8_TXS0102_40X60_0-4]  29.41 103.38 180 top
U40  SN74LVC07ADGVR  [TVSOP14_15-74_180X150_1-2]  14.34 87.83 270 top
U41  LM4040B25IDCKR  [SC70-5_1-1]  43.64 97.48 180 top
U43  SN74LVC1G11DRYR  [SON6_SN74LVC2G17_40X60_0-6]  97.31 91.09 180 top
U46  TLV75801PDBVT  [SOT23-5_1-5]  49.77 80.57 270 top
U48  TM4C1294NCPDTT3R  [TQFP128_15-74_550X550_1-2]  37.33 87.61 180 top
U49  MTFC32GAZAQHD-IT  [VFBGA153_19-68_460X520_0-9]  107.21 74.3 90 top
U51  TXS0102DQER  [X2SON8_TXS0102_40X60_0-4]  22.94 79.35 180 top
U54  SN74LVC1G11DRYR  [SON6_SN74LVC2G17_40X60_0-6]  20.29 60.73 0 top
U55  TPS79601DRBR  [SON8_25-59_130X130_1]  28.63 73.94 270 top
U56  TPS6522435RAHRQ1  [VQFN-HR36-35_TPS65224_240X200_1]  39.82 56.36 0 top
U57  TS3DDR3812RUAR  [TQFN42_19-68_140X360_0-8]  97.58 82.13 0 bottom
U59  TPS7A2118PQWDRBRQ1  [SON8_25-59_130X130_1]  62.98 61.03 0 top
U60  TPD4E004DRYR  [SON6_19-68_40X60_PB_0-6]  18.92 50.24 0 top
U61  93LC46B  [MSOP8_25-59_125X125_1-1]  52.85 24.22 270 top
U62  25.000MHz  [VSON4_LMK6CE_80X100_SMD_1]  79.16 53.4 180 bottom
U64  FT4232HL  [LQFP64_19-68_390X390_1-6]  61.72 32.1 90 top
U65  LMK1C1103PWR  [TSSOP8_25-59_125X180_1-2]  67.17 54.59 0 bottom
U66  TPS73533DRVR  [SON6_25-59_85X85]  58.97 9.7 270 top
U67  TPD2E001DRLR  [SOT553-5_0-6]  65.81 8.87 180 top
U68  SN74LVC1G11DRYR  [SON6_SN74LVC2G17_40X60_0-6]  69.91 50.37 0 top
U69  W25Q80DVSNIG  [SOIC8_1-8]  39.57 28.01 0 top
U71  SN74LVC1G32DPWR  [X2SON5_TLV7021_30X30_0-4]  34.84 35.29 90 top
U73  TPS22810DRVT  [SON6_25-59_85X85_0-8]  29.97 21.46 90 top
U75  SN74LVC1G08DBVRE4  [SOT23-5]  64.55 161.06 180 bottom
U76  TAD5212IRGER  [QFN24_TAD5212IRGER_160X160_1]  110.59 153.07 180 bottom
U77  TAD5212IRGER  [QFN24_TAD5212IRGER_160X160_1]  93.19 153.07 180 bottom
U81  SN74AVC8T245RHL  [QFN24_19-68_220X140_1]  97.83 123.18 90 bottom
U82  TCA6424ARGJR  [QFN32_19-68_200X200]  90.31 123.18 180 bottom
U83  SN74AVC8T245RHL  [QFN24_19-68_220X140_1]  81.22 122.52 270 bottom
U86  SN74LVC1G11DRYR  [SON6_SN74LVC2G17_40X60_0-6]  24.07 64.87 90 bottom
U87  SN74LVC1G32DPWR  [X2SON5_TLV7021_30X30_0-4]  42.25 114.22 0 bottom
U88  SN74LVC1G32DPWR  [X2SON5_TLV7021_30X30_0-4]  47.1 112.77 0 bottom
U90  SN74AVC2T244DQMR  [X2SON8_15-74_70X50]  44.3 106.62 90 bottom
U91  INA228AIDGSR  [MSOP10_19-68_120X120_1-1]  55.86 57.23 270 bottom
U92  INA231AIYFDR  [DSBGA12_15-74_60X70_0-4]  55.86 57.23 180 bottom
U93  SN74LVC1G04DCKR  [SC70-5]  26.86 94.81 270 bottom
U97  SN74AVC4T245RSVR  [UQFN16_TMUX1574_70X100_0-6#2]  33.03 92.38 90 bottom
U98  SN74LVC3G17DCUR  [VSSOP8_19-68_85X95_0-9#2]  49.67 74.17 180 bottom
U102  TXS0102DQER  [X2SON8_TXS0102_40X60_0-4]  33.56 88.42 0 bottom
U107  TCA9517DR  [SOIC8_1-8]  17.51 73.47 270 bottom
U109  SN74AVC2T244DQMR  [X2SON8_15-74_70X50]  32.49 83.62 90 bottom
U110  SN74AVC4T245RSVR  [UQFN16_TMUX1574_70X100_0-6#2]  36.38 83.57 0 bottom
U113  INA231AIYFDR  [DSBGA12_15-74_60X70_0-4]  30.08 61.96 0 bottom
U114  INA228AIDGSR  [MSOP10_19-68_120X120_1-1]  30.08 61.96 90 bottom
U115  INA231AIYFDR  [DSBGA12_15-74_60X70_0-4]  49.01 51.58 0 bottom
U116  INA228AIDGSR  [MSOP10_19-68_120X120_1-1]  49.01 51.58 90 bottom
U117  SN74AVC4T245RSVR  [UQFN16_TMUX1574_70X100_0-6#2]  48.25 32.77 0 bottom
U118  INA228AIDGSR  [MSOP10_19-68_120X120_1-1]  51.64 42.97 90 bottom
U119  INA231AIYFDR  [DSBGA12_15-74_60X70_0-4]  51.64 42.97 0 bottom
U120  SN74LVC1G11DRYR  [SON6_SN74LVC2G17_40X60_0-6]  113.17 47.55 180 bottom
U123  INA231AIYFDR  [DSBGA12_15-74_60X70_0-4]  40.81 36.96 0 bottom
U124  INA228AIDGSR  [MSOP10_19-68_120X120_1-1]  40.81 36.96 90 bottom
U125  SN74AVC4T245RSVR  [UQFN16_TMUX1574_70X100_0-6#2]  63.52 30.04 90 bottom
U126  SN74AVC4T245RSVR  [UQFN16_TMUX1574_70X100_0-6#2]  70.75 28.07 180 bottom
U127  TPS62824DMQR  [VSONHR6_TPS62826_60X60_1]  91.66 31.55 0 bottom
U129  TPS65988DHRSHR  [VQFN56_TPS65987D_280X280_1]  40.05 20.38 90 bottom
U132  TVS2200DRVR  [SON6_25-59_85X85_0-8]  45.95 10.85 0 bottom
U133  TVS2200DRVR  [SON6_25-59_85X85_0-8]  39.04 10.15 180 bottom
U134  LM61460AASQRJRRQ1  [VQFNHR14_LM61460_160X140_1]  18.82 16.15 90 top
U135  TPS74601PDRVR  [SON6_25-59_85X85_0-8#2]  52.52 80.24 180 bottom
U136  AM275x_EVM_SoC  [BGA361_31-49_630X630_1-5]  74.9 84.45 90 top
U140  S80KS5122  [BGA24_39-37_240X310_1]  56.53 97.61 90 top
U2345  TXB0108PWR  [TSSOP20_25-59_260X180]  108.3 117.11 90 bottom
U2346  TMUX1136DQAR  [USON10_TMUX1204_40X100_0-6]  86.96 136.62 90 top
U2347  TS5A3357QDCURQ1  [VSSOP8_19-68_85X95_0-9]  100.83 55.12 180 top
U2348  SN74LVC1G08DBVRE4  [SOT23-5#2]  56.69 108.36 270 top
U2349  TPD4E02B04DQAR  [USON10_TPD4E05U_40X100_0-6]  128.18 59.99 180 bottom
U2350  TPD4E02B04DQAR  [USON10_TPD4E05U_40X100_0-6]  127.64 51.79 180 bottom
U2351  TMUX1136DQAR  [USON10_TMUX1204_40X100_0-6]  57.94 42.57 90 top
U2352  TMUX1136DQAR  [USON10_TMUX1204_40X100_0-6]  66.81 42.96 270 top
U2353  SN74AVC4T245RSVR  [UQFN16_TMUX1574_70X100_0-6]  77.57 47.26 180 top
U2355  SN74LVC1G07DBVR  [SOT23-5#2]  45.29 118.63 90 top
U2356  TMUX1136DQAR  [USON10_TMUX1204_40X100_0-6]  25.8 51 0 top
U2357  TMP411ADR  [SOIC8_1-8]  90.95 101.98 90 top
U2358  CAT24M01WI-GT3  [SOIC8_1-8]  51.9 132.94 270 top
U3068  TCAN1043ADYYRQ1  [SOT23-14_1-1]  38.54 159 180 top
U3070  SN74LVC1G17DCKR  [SC70-5]  65.88 123.72 0 top
U3072  SN74CBTLV16292GR  [TSSOP56_19-68_560X240_1-2]  107 107.24 90 bottom
U3076  TPS22919DCKR  [SC70-6_1-1]  20.5 65.8 90 top
U3077  TXS0104EPWR  [TSSOP14_25-59_205X180_1-2]  91.22 66.33 0 top
U3078  INA228AIDGSR  [MSOP10_19-68_120X120_1-1]  58.02 64.99 90 bottom
U3079  INA228AIDGSR  [MSOP10_19-68_120X120_1-1]  44.02 73.22 90 bottom
U3080  INA231AIYFDR  [DSBGA12_15-74_60X70_0-4]  58.02 64.99 270 bottom
U3081  INA231AIYFDR  [DSBGA12_15-74_60X70_0-4]  44.05 73.12 270 bottom
U3083  SN74AVC2T244DQMR  [X2SON8_15-74_70X50]  106.84 58.15 90 top
U3084  LMK1C1102PWR  [TSSOP8_25-59_125X180_1-2]  113.09 56.02 90 top
U3086  SN74LV1T125DCKR  [SC70-5_1-1#2]  64.17 51.91 180 top
U3087  SN74LVC1G32DPWR  [X2SON5_TLV7021_30X30_0-4]  61.87 54.54 90 top
Y1  24.576MHz  [XTAL4_ABMM_280X200_SMD_1-3]  80.56 58.98 90 top
Y3  25.000MHz  [XTAL4_XRCGB-FM_80X60_SMD_0-7]  59.4 75.8 270 top
Y4  32.768KHz  [XTAL_ECS-32_130X60_SMD_0-9]  58.23 74.82 90 bottom
Y5  16.000MHz  [XTAL4_XRCGB-FM_80X60_SMD_0-7]  26.06 84.36 90 top
Y6  12.000MHz  [XTAL_ABM3_205X130_SMD_1-4]  57.92 21.34 0 top
Y8  24.576MHz  [XTAL4_ABM3B_210X130_SMD]  67.13 69.82 180 top

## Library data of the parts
C1-C3 C11-C18 C20-C33 C35 C37 C38 C42 C43 C45-C57 C60-C78 C81 C82 C84-C90 C92 C93 C95-C105 C107 C109 C121 C122 C126 C128-C130 C133-C138 C140-C142 C146-C151 C160 C161 C164 C165 C167-C172 C174-C176 C182 C188 C190 C192 C197 C201-C203 C205 C207-C209 C213 C215-C217 C221-C229 C231-C236 C240-C251 C254-C267 C269-C293 C295 C300-C303 C305-C310 C312 C317-C327 C329-C338 C340-C374 C378 C379 C382-C391 C393-C395 C408 C409 C414-C417 C421 C427-C430 C432 C434 C437 C440 C441 C443 C445-C449 C451 C453-C455 C460-C463 C465-C471 C473 C477 C478 C483-C485 C488-C490 C493-C495 C497 C498 C500-C506 C508 C509 C511 C512 C514-C518 C520 C521 C524 C525 C527-C529 C532-C538 C546 C547 C555 C559-C561 C565 C572 C574-C576 C592 C593 C597-C599 C602-C618 C620 C622 C631 C638-C644 C646-C655 C657-C660 C662 C663 C787 C3494 C3497 C3625 C3627-C3631 C3636-C3639 C3642-C3645 C3647 C3649 C3652 C3653 C3655-C3661 C3692 C3694-C3698 C3701-C3721 C3724-C3733 C3738 C3740-C3747 C3750-C3764 C3767-C3769 C3771-C3774 = CAP
D1 D3 D11-D14 D18 = DIODE_SOD323
D2 D6 = DIODE_ZENER_SOT23_13
D5 = DIODE_BAT54CW_SOT323-123
D7 D8 D16 D17 = DIODE_TVS_DUAL
D9 = DIODE_ESD122DMXR
FL1 FL2 FL4 FL6 FL8-FL10 FL13 FL17-FL23 = EMIFILTER_IND
J1-J4 = CON_AUDIOJACK6_STX-4235-3/3
J7 J10 J16 J32-J34 = HEADER_2X1
J9 J29 = HEADER_3X1
J12 J13 = CON40X2_SAMTEC
J14 = HEADER_10X2_FTR-06
J17 J22 = CON_USB_MINI-B
J18 J19 = CON_BTOB_24X2_M_SH4
J21 = HEADER_5X2
J24 J25 = CON_USB-C_24_1240183621
J26 = CON_SDCARD9_MEM2075-00-140
J28 = HEADER_4X2
J31 = HEADER_6X2
L2-L7 L11 L24 = INDUCTOR
L10 = INDUCTOR_DLW31S
LD1-LD7 LD9 LD10 LD13 LD14 = DIODE_LED
Q1 Q5 Q10 = MOSFET_CSD17313Q2
Q2 = NPN_123_SOT23-3
Q3 Q4 = MOSFET_BSS138W
Q7 Q12 = MOSFET_IRLML6401TR
Q8 Q9 = MOSFET_CSD25310Q2
R3-R10 R17 R18 R20-R38 R46 R54-R58 R60-R70 R75 R76 R78 R81-R85 R88 R90 R93 R94 R97 R98 R102 R107 R108 R112 R115-R119 R121-R141 R143 R145-R160 R166 R170 R180 R195 R202 R203 R205 R210-R214 R216-R221 R224 R225 R227 R229-R238 R240-R243 R246 R249 R252-R256 R258-R260 R268 R270-R272 R275-R278 R280-R301 R303-R308 R310 R311 R313 R314 R317-R324 R326 R328-R331 R333 R335-R338 R340-R349 R351 R352 R355-R364 R366 R367 R371 R373-R375 R377 R378 R381 R382 R385 R386 R390 R395 R398-R416 R418-R423 R429-R433 R435 R438-R452 R454 R456 R457 R461 R464 R465 R476 R480 R482 R483 R485 R487 R489 R490 R504 R505 R507 R510-R513 R515-R517 R519-R526 R531 R533 R534 R536 R539-R556 R559-R562 R564-R566 R568 R569 R571 R572 R575 R576 R578-R580 R582-R586 R590-R593 R596-R598 R601-R616 R618 R620-R639 R641-R646 R651-R658 R660 R662 R664 R665 R669 R672-R682 R684 R685 R3028 R3651-R3653 R3661 R3720 R3723-R3727 R3731 R3736 R3933 R5213 R5215 R5216 R5635-R5639 R5649 R5650 R5659 R5670 R5671 R5681 R5684-R5688 R5692 R5693 R5697-R5699 R5709-R5717 R5720-R5727 R5730-R5737 R5740-R5748 R5750 R5751 R5753 R5754 R5756 R5758-R5761 R5764 R5766 R5767 R5773-R5778 R5780-R5782 R5784 R5785 R5788-R5793 R5795-R5800 R5805 R5806 R5808 R5810 R5820-R5825 = RESISTOR
R73 R74 R89 R453 R538 R3732 R3733 = RESISTOR: signal model: RESISTOR_RES0201_0-5_22E_1%_22E_1%
R176 R177 R190 R191 R228 R239 R261 R491-R495 R498-R500 R506 R509 R518 R527-R530 R535 R537 R5640-R5645 R5647 R5652 R5654-R5658 R5660-R5667 R5672-R5676 R5682 R5689 R5694-R5696 R5718 R5719 R5728 R5738 R5757 = RESISTOR: signal model: RESISTOR_RES0201_0-5_0E_0E
R178 R179 R5646 R5648 R5651 R5653 R5668 R5669 R5677 R5683 R5752 = RESISTOR: signal model: RESISTOR_RES0402_0-5_22E_22E
R197 R206 R558 R5811-R5819 R5826-R5829 = RESISTOR: signal model: RESISTOR_RES0402_0-5_0E_0E
R262-R264 R266 R267 R269 = RESISTOR: signal model: RESISTOR_RES0201_0-5_10K_10K
R265 R316 R327 R334 R581 R5786 R5787 = RESISTOR-4TERM
RA2 RA5-RA7 = RESARR_ISO4
RA3 RA4 RA8 RA9 = RESARR_ISO4: signal model: RESARR_ISO4_RESA_EXB_0201-4_0-5_0E
SW1 SW2 = SW16_CHS-08A
SW3 = SW4_GDH02S04
SW5-SW8 SW10 = 7914G-1-000E _7914G
SW9 = SW2_CHS-01TA
SW11 = SWTACT_CAS-120TA
TP1 TP2 TP5 TP6 TP8 TP9 TP11 TP12 TP14 TP17-TP23 TP25-TP27 TP31-TP33 TP36-TP42 TP44-TP46 TP49-TP56 TP58-TP81 TP83 TP85-TP87 TP89 TP91-TP100 TP103 TP104 TP106-TP117 TP585-TP594 TP597 = TESTPOINT
U2 U43 U54 U68 U86 U120 = SN74LVC1G11DCKR_SC70-6
U4 = TPS22918DBVR_SOT23-6
U5 U6 U76 U77 = TAD5212IRGER_QFN24
U7 U8 = PCM6240QRTVRQ1_WQFN32
U10 = TPD6E001RSE_UQFN10
U11 = TCA9406DCUR_VSSOP8
U12 U67 = TPD2E001DRLR_SOT-5
U14 U23 U26 U27 U75 U2348 = SN74LVC1G08DBVRE4_SOT23-5
U15 = CDCE6214_WFQFN24
U18 = TCA6416ARTWR_WQFN24
U21 U82 = TCA6424ARGJR_QFN32
U25 U107 = TCA9517DGKR_VSSOP8
U28 = S28HS512T_BGA24
U29 U90 U109 U3083 = SN74AVC2T244DQMR_X2SON8
U39 U51 U102 = TXS0102DQX_SON8
U40 = 74HC7014X_SOIC14
U41 = LM4040B25IDCKR_SC70-5
U46 = TLV75801P_SOT23-5
U48 = TM4C1294NCPDTT3R_TQFP128
U49 = MTFC16GAPALBH_TFBGA153
U55 = TPS79601DRBR_SON8
U56 = TPS65224_VQFN-HR36
U57 = TS3DDR3812RUAR_WQFN42
U59 = TPS7A21_SON8
U60 = TPD4E004_SON6
U61 = 93LC46B_MSOP8
U62 = OSC4_LMK6CE
U64 = FT4232H_LQFP64
U65 = LMK1C1103_TSSOP8
U66 = TPS73501DRVR_SON6
U69 = W25Q80BWSNIG_SOIC8
U71 U87 U88 U3087 = SN74LVC1G32_X2SON5
U73 = TPS22810DRVT_WSON6
U81 U83 = SN74AVC8T245RHL_QFN24
U91 U114 U116 U118 U124 U3078 U3079 = INA226AIDGS_MSOP10
U92 U113 U115 U119 U123 U3080 U3081 = INA231_DSBGA12
U93 = SN74LVC1G04DCKR_SC70-5
U97 U110 U117 U125 U126 U2353 = SN74AVC4T245RSV_UQFN16
U98 = SN74LVC3G17DCUR_VSSOP8
U127 = TPS62827DMQR_VSONHR6
U129 = TPS65988DJ_VQFN56
U132 U133 = TVS2200_WSON6
U134 = LM61460_VQFNHR14
U135 = TPS74501_WSON6
U136 = AM275X_EVM_SOC_BGA361
U140 = S80KS5122GABHM_BGA24
U2345 = TXB0108PWR_TSSOP20
U2346 U2351 U2352 U2356 = TMUX1136_USON10
U2347 = TS5A3357QDCURQ1_VSSOP8
U2349 U2350 = TPD4E02B04DQAR_USON10
U2355 = SN74LVC1G07DBVR_SOT23-5
U2357 = TMP411ADR_SOIC8
U2358 = AT24HC04B-TH-B_TSSOP8
U3068 = TCAN1043DQ1_SOIC14
U3070 = SN74LVC1G17DCKR_SC70-5
U3072 = SN74CBTLV16292GR_TSSOP56
U3076 = TPS22919_SC70-6
U3077 = TXS0104EPWR_TSSOP14
U3084 = LMK1C1102_TSSOP8
U3086 = SN74LV1T125DCKR_SC70-5
Y1 = CRY4_ABMM
Y3 Y5 Y8 = CRY4_13
Y4 Y6 = CRY

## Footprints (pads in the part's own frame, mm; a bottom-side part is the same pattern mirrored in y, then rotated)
BGA24_39-37_240X310_1
  round 0.356 smd: A2(-1,2) A3(0,2) A4(1,2) A5(2,2) B1(-2,1) B2(-1,1) B3(0,1) B4(1,1) B5(2,1) C1(-2,0) C2(-1,0) C3(0,0) C4(1,0) C5(2,0) D1(-2,-1) D2(-1,-1) D3(0,-1) D4(1,-1) D5(2,-1) E1(-2,-2) E2(-1,-2) E3(0,-2) E4(1,-2) E5(2,-2)
BGA361_31-49_630X630_1-5
  round 0.457 smd: A1(-7.2,7.2) A2(-6.4,7.2) A3(-5.6,7.2) A4(-4.8,7.2) A5(-4,7.2) A6(-3.2,7.2) A7(-2.4,7.2) A8(-1.6,7.2) A9(-0.8,7.2) A10(0,7.2) A11(0.8,7.2) A12(1.6,7.2) A13(2.4,7.2) A14(3.2,7.2) A15(4,7.2) A16(4.8,7.2) A17(5.6,7.2) A18(6.4,7.2) A19(7.2,7.2) B1(-7.2,6.4) B2(-6.4,6.4) B3(-5.6,6.4) B4(-4.8,6.4) B5(-4,6.4) B6(-3.2,6.4) B7(-2.4,6.4) B8(-1.6,6.4) B9(-0.8,6.4) B10(0,6.4) B11(0.8,6.4) B12(1.6,6.4) B13(2.4,6.4) B14(3.2,6.4) B15(4,6.4) B16(4.8,6.4) B17(5.6,6.4) B18(6.4,6.4) B19(7.2,6.4) C1(-7.2,5.6) C2(-6.4,5.6) C3(-5.6,5.6) C4(-4.8,5.6) C5(-4,5.6) C6(-3.2,5.6) C7(-2.4,5.6) C8(-1.6,5.6) C9(-0.8,5.6) C10(0,5.6) C11(0.8,5.6) C12(1.6,5.6) C13(2.4,5.6) C14(3.2,5.6) C15(4,5.6) C16(4.8,5.6) C17(5.6,5.6) C18(6.4,5.6) C19(7.2,5.6) D1(-7.2,4.8) D2(-6.4,4.8) D3(-5.6,4.8) D4(-4.8,4.8) D5(-4,4.8) D6(-3.2,4.8) D7(-2.4,4.8) D8(-1.6,4.8) D9(-0.8,4.8) D10(0,4.8) D11(0.8,4.8) D12(1.6,4.8) D13(2.4,4.8) D14(3.2,4.8) D15(4,4.8) D16(4.8,4.8) D17(5.6,4.8) D18(6.4,4.8) D19(7.2,4.8) E1(-7.2,4) E2(-6.4,4) E3(-5.6,4) E4(-4.8,4) E5(-4,4) E6(-3.2,4) E7(-2.4,4) E8(-1.6,4) E9(-0.8,4) E10(0,4) E11(0.8,4) E12(1.6,4) E13(2.4,4) E14(3.2,4) E15(4,4) E16(4.8,4) E17(5.6,4) E18(6.4,4) E19(7.2,4) F1(-7.2,3.2) F2(-6.4,3.2) F3(-5.6,3.2) F4(-4.8,3.2) F5(-4,3.2) F6(-3.2,3.2) F7(-2.4,3.2) F8(-1.6,3.2) F9(-0.8,3.2) F10(0,3.2) F11(0.8,3.2) F12(1.6,3.2) F13(2.4,3.2) F14(3.2,3.2) F15(4,3.2) F16(4.8,3.2) F17(5.6,3.2) F18(6.4,3.2) F19(7.2,3.2) G1(-7.2,2.4) G2(-6.4,2.4) G3(-5.6,2.4) G4(-4.8,2.4) G5(-4,2.4) G6(-3.2,2.4) G7(-2.4,2.4) G8(-1.6,2.4) G9(-0.8,2.4) G10(0,2.4) G11(0.8,2.4) G12(1.6,2.4) G13(2.4,2.4) G14(3.2,2.4) G15(4,2.4) G16(4.8,2.4) G17(5.6,2.4) G18(6.4,2.4) G19(7.2,2.4) H1(-7.2,1.6) H2(-6.4,1.6) H3(-5.6,1.6) H4(-4.8,1.6) H5(-4,1.6) H6(-3.2,1.6) H7(-2.4,1.6) H8(-1.6,1.6) H9(-0.8,1.6) H10(0,1.6) H11(0.8,1.6) H12(1.6,1.6) H13(2.4,1.6) H14(3.2,1.6) H15(4,1.6) H16(4.8,1.6) H17(5.6,1.6) H18(6.4,1.6) H19(7.2,1.6) J1(-7.2,0.8) J2(-6.4,0.8) J3(-5.6,0.8) J4(-4.8,0.8) J5(-4,0.8) J6(-3.2,0.8) J7(-2.4,0.8) J8(-1.6,0.8) J9(-0.8,0.8) J10(0,0.8) J11(0.8,0.8) J12(1.6,0.8) J13(2.4,0.8) J14(3.2,0.8) J15(4,0.8) J16(4.8,0.8) J17(5.6,0.8) J18(6.4,0.8) J19(7.2,0.8) K1(-7.2,0) K2(-6.4,0) K3(-5.6,0) K4(-4.8,0) K5(-4,0) K6(-3.2,0) K7(-2.4,0) K8(-1.6,0) K9(-0.8,0) K10(0,0) K11(0.8,0) K12(1.6,0) K13(2.4,0) K14(3.2,0) K15(4,0) K16(4.8,0) K17(5.6,0) K18(6.4,0) K19(7.2,0) L1(-7.2,-0.8) L2(-6.4,-0.8) L3(-5.6,-0.8) L4(-4.8,-0.8) L5(-4,-0.8) L6(-3.2,-0.8) L7(-2.4,-0.8) L8(-1.6,-0.8) L9(-0.8,-0.8) L10(0,-0.8) L11(0.8,-0.8) L12(1.6,-0.8) L13(2.4,-0.8) L14(3.2,-0.8) L15(4,-0.8) L16(4.8,-0.8) L17(5.6,-0.8) L18(6.4,-0.8) L19(7.2,-0.8) M1(-7.2,-1.6) M2(-6.4,-1.6) M3(-5.6,-1.6) M4(-4.8,-1.6) M5(-4,-1.6) M6(-3.2,-1.6) M7(-2.4,-1.6) M8(-1.6,-1.6) M9(-0.8,-1.6) M10(0,-1.6) M11(0.8,-1.6) M12(1.6,-1.6) M13(2.4,-1.6) M14(3.2,-1.6) M15(4,-1.6) M16(4.8,-1.6) M17(5.6,-1.6) M18(6.4,-1.6) M19(7.2,-1.6) N1(-7.2,-2.4) N2(-6.4,-2.4) N3(-5.6,-2.4) N4(-4.8,-2.4) N5(-4,-2.4) N6(-3.2,-2.4) N7(-2.4,-2.4) N8(-1.6,-2.4) N9(-0.8,-2.4) N10(0,-2.4) N11(0.8,-2.4) N12(1.6,-2.4) N13(2.4,-2.4) N14(3.2,-2.4) N15(4,-2.4) N16(4.8,-2.4) N17(5.6,-2.4) N18(6.4,-2.4) N19(7.2,-2.4) P1(-7.2,-3.2) P2(-6.4,-3.2) P3(-5.6,-3.2) P4(-4.8,-3.2) P5(-4,-3.2) P6(-3.2,-3.2) P7(-2.4,-3.2) P8(-1.6,-3.2) P9(-0.8,-3.2) P10(0,-3.2) P11(0.8,-3.2) P12(1.6,-3.2) P13(2.4,-3.2) P14(3.2,-3.2) P15(4,-3.2) P16(4.8,-3.2) P17(5.6,-3.2) P18(6.4,-3.2) P19(7.2,-3.2) R1(-7.2,-4) R2(-6.4,-4) R3(-5.6,-4) R4(-4.8,-4) R5(-4,-4) R6(-3.2,-4) R7(-2.4,-4) R8(-1.6,-4) R9(-0.8,-4) R10(0,-4) R11(0.8,-4) R12(1.6,-4) R13(2.4,-4) R14(3.2,-4) R15(4,-4) R16(4.8,-4) R17(5.6,-4) R18(6.4,-4) R19(7.2,-4) T1(-7.2,-4.8) T2(-6.4,-4.8) T3(-5.6,-4.8) T4(-4.8,-4.8) T5(-4,-4.8) T6(-3.2,-4.8) T7(-2.4,-4.8) T8(-1.6,-4.8) T9(-0.8,-4.8) T10(0,-4.8) T11(0.8,-4.8) T12(1.6,-4.8) T13(2.4,-4.8) T14(3.2,-4.8) T15(4,-4.8) T16(4.8,-4.8) T17(5.6,-4.8) T18(6.4,-4.8) T19(7.2,-4.8) U1(-7.2,-5.6) U2(-6.4,-5.6) U3(-5.6,-5.6) U4(-4.8,-5.6) U5(-4,-5.6) U6(-3.2,-5.6) U7(-2.4,-5.6) U8(-1.6,-5.6) U9(-0.8,-5.6) U10(0,-5.6) U11(0.8,-5.6) U12(1.6,-5.6) U13(2.4,-5.6) U14(3.2,-5.6) U15(4,-5.6) U16(4.8,-5.6) U17(5.6,-5.6) U18(6.4,-5.6) U19(7.2,-5.6) V1(-7.2,-6.4) V2(-6.4,-6.4) V3(-5.6,-6.4) V4(-4.8,-6.4) V5(-4,-6.4) V6(-3.2,-6.4) V7(-2.4,-6.4) V8(-1.6,-6.4) V9(-0.8,-6.4) V10(0,-6.4) V11(0.8,-6.4) V12(1.6,-6.4) V13(2.4,-6.4) V14(3.2,-6.4) V15(4,-6.4) V16(4.8,-6.4) V17(5.6,-6.4) V18(6.4,-6.4) V19(7.2,-6.4) W1(-7.2,-7.2) W2(-6.4,-7.2) W3(-5.6,-7.2) W4(-4.8,-7.2) W5(-4,-7.2) W6(-3.2,-7.2) W7(-2.4,-7.2) W8(-1.6,-7.2) W9(-0.8,-7.2) W10(0,-7.2) W11(0.8,-7.2) W12(1.6,-7.2) W13(2.4,-7.2) W14(3.2,-7.2) W15(4,-7.2) W16(4.8,-7.2) W17(5.6,-7.2) W18(6.4,-7.2) W19(7.2,-7.2)
CAP0201_0-5
  rect 0.356x0.33 smd: 1(-0.28,0) 2(0.28,0)
CAP0201_0-75
  rect 0.457x0.432 smd: 1(-0.34,0) 2(0.34,0)
CAP0402_0-75
  rect 0.559x0.635 smd: 1(-0.49,0) 2(0.49,0)
CAP0402_1
  rect 0.559x0.635 smd: 1(-0.49,0) 2(0.49,0)
CAP0603_1
  rect 0.94x1.016 smd: 1(-0.8,0) 2(0.8,0)
CAP0805_1-5
  rect 0.94x1.346 smd: 1(-0.8,0) 2(0.8,0)
CAP0805_1-5#2
  rect 1.143x1.448 smd: 1(-0.9,0) 2(0.9,0)
CAP1206_1-75
  rect 1.143x1.803 smd: 1(-1.5,0) 2(1.5,0)
CAP1206_2
  rect 1.143x1.803 smd: 1(-1.5,0) 2(1.5,0)
CAP1210_2-75
  rect 0.94x2.591 smd: 1(-1.4,0) 2(1.4,0)
CON_40X2_QSE-040-01_S_S_S
  round 0.889 hole 1.016 unplated: (-20.07,2.665) (20.07,2.665)
  rect 0.406x2.286 smd: 1(-17.6,-2.865) 2(-17.6,2.865) 3(-16.8,-2.865) 4(-16.8,2.865) 5(-16,-2.865) 6(-16,2.865) 7(-15.2,-2.865) 8(-15.2,2.865) 9(-14.4,-2.865) 10(-14.4,2.865) 11(-13.6,-2.865) 12(-13.6,2.865) 13(-12.8,-2.865) 14(-12.8,2.865) 15(-12,-2.865) 16(-12,2.865) 17(-11.2,-2.865) 18(-11.2,2.865) 19(-10.4,-2.865) 20(-10.4,2.865) 21(-9.6,-2.865) 22(-9.6,2.865) 23(-8.8,-2.865) 24(-8.8,2.865) 25(-8,-2.865) 26(-8,2.865) 27(-7.2,-2.865) 28(-7.2,2.865) 29(-6.4,-2.865) 30(-6.4,2.865) 31(-5.6,-2.865) 32(-5.6,2.865) 33(-4.8,-2.865) 34(-4.8,2.865) 35(-4,-2.865) 36(-4,2.865) 37(-3.2,-2.865) 38(-3.2,2.865) 39(-2.4,-2.865) 40(-2.4,2.865) 41(2.4,-2.865) 42(2.4,2.865) 43(3.2,-2.865) 44(3.2,2.865) 45(4,-2.865) 46(4,2.865) 47(4.8,-2.865) 48(4.8,2.865) 49(5.6,-2.865) 50(5.6,2.865) 51(6.4,-2.865) 52(6.4,2.865) 53(7.2,-2.865) 54(7.2,2.865) 55(8,-2.865) 56(8,2.865) 57(8.8,-2.865) 58(8.8,2.865) 59(9.6,-2.865) 60(9.6,2.865) 61(10.4,-2.865) 62(10.4,2.865) 63(11.2,-2.865) 64(11.2,2.865) 65(12,-2.865) 66(12,2.865) 67(12.8,-2.865) 68(12.8,2.865) 69(13.6,-2.865) 70(13.6,2.865) 71(14.4,-2.865) 72(14.4,2.865) 73(15.2,-2.865) 74(15.2,2.865) 75(16,-2.865) 76(16,2.865) 77(16.8,-2.865) 78(16.8,2.865) 79(17.6,-2.865) 80(17.6,2.865)
  rect 2.794x0.432 smd: 81(-18.07,-0.005) 84(-1.94,-0.005) 85(1.93,-0.005) 88(18.06,-0.005)
  rect 4.724x0.432 smd: 82(-13.18,-0.005) 83(-6.83,-0.005) 86(6.82,-0.005) 87(13.17,-0.005)
CON_AV6_STX-4235-3-3_S_R_T_26
  oval 1.854x3.886 hole 1.981x4.013 unplated: (-7,0) (-3,0)
  rect 2.21x2.21 hole 1.524: 1A(0,0)
  round 2.21 hole 1.524: 1B(-10,0) 2A(1.25,7.5) 2B(-10,5) 5A(-11.25,7.5) 5B(0,5)
CON_BTOB2X24_DF40GB-48DP_P_S_S_1-3
  rect 0.229x0.66 smd: 1(-4.6,-1.355) 2(-4.6,1.355) 3(-4.2,-1.355) 4(-4.2,1.355) 5(-3.8,-1.355) 6(-3.8,1.355) 7(-3.4,-1.355) 8(-3.4,1.355) 9(-3,-1.355) 10(-3,1.355) 11(-2.6,-1.355) 12(-2.6,1.355) 13(-2.2,-1.355) 14(-2.2,1.355) 15(-1.8,-1.355) 16(-1.8,1.355) 17(-1.4,-1.355) 18(-1.4,1.355) 19(-1,-1.355) 20(-1,1.355) 21(-0.6,-1.355) 22(-0.6,1.355) 23(-0.2,-1.355) 24(-0.2,1.355) 25(0.2,-1.355) 26(0.2,1.355) 27(0.6,-1.355) 28(0.6,1.355) 29(1,-1.355) 30(1,1.355) 31(1.4,-1.355) 32(1.4,1.355) 33(1.8,-1.355) 34(1.8,1.355) 35(2.2,-1.355) 36(2.2,1.355) 37(2.6,-1.355) 38(2.6,1.355) 39(3,-1.355) 40(3,1.355) 41(3.4,-1.355) 42(3.4,1.355) 43(3.8,-1.355) 44(3.8,1.355) 45(4.2,-1.355) 46(4.2,1.355) 47(4.6,-1.355) 48(4.6,1.355)
  rect 0.356x0.711 smd: SH1(-5.135,-0.86) SH2(-5.135,0.86) SH3(5.135,-0.86) SH4(5.135,0.86)
CON_MUSBB5_629105150521_S_R_S_2-7
  round 0.686 hole 0.813 unplated: (-2.5,1.848) (2.5,1.848)
  rect 0.457x1.295 smd: 1(-1.3,2.948) 2(-0.65,2.948) 3(0,2.948) 4(0.65,2.948) 5(1.3,2.948)
  oval 1.448x2.311 hole 0.864x1.727: 6(-3.725,2.898) 7(3.725,2.898)
  oval 1.143x1.803 hole 0.559x1.219: 8(-3.875,-0.902) 9(3.875,-0.902)
CON_SD9_MEM2052-00-195-00_S_R_S_2
  rect 0.787x1.499 smd: 1(1.94,-3.66) 2(0.84,-3.26) 3(-0.26,-3.66) 4(-1.36,-3.86) 5(-2.46,-3.66) 6(-3.56,-3.86) 7(-4.66,-3.66) 8(-5.76,-3.66)
  rect 0.991x0.94 smd: 9(-3.56,7.425)
  rect 1.397x1.905 smd: SH1(6.6,-6.95) SH2(-6.55,-5.95)
  rect 1.295x1.397 smd: SH3(0.75,7.2)
  rect 1.194x1.397 smd: SH4(-5.008,7.2)
CON_USBC24_2012670_S_R_S_3-9
  rect 0.305x0.762 smd: A1(-3,4.056) A2(-2.5,4.056) A3(-2,4.056) A4(-1.5,4.056) A5(-1,4.056) A6(-0.5,4.056) A7(0.5,4.056) A8(1,4.056) A9(1.5,4.056) A10(2,4.056) A11(2.5,4.056) A12(3,4.056) B2(2.25,2.356) B3(1.75,2.356) B4(1.25,2.356) B5(0.75,2.356) B6(0.25,2.356) B7(-0.25,2.356) B8(-0.75,2.356) B9(-1.25,2.356) B10(-1.75,2.356) B11(-2.25,2.356)
  rect 0.94x0.762 smd: B1(3.05,2.356) B12(-3.05,2.356)
  oval 1.194x2.21 hole 0.61x1.575: SH1(-4.32,3.246) SH2(4.32,3.246)
  oval 1.194x3.708 hole 0.61x2.083: SH3(4.62,-2.114) SH4(-4.62,-2.114)
